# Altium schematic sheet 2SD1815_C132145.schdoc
size 127 x 101 mm
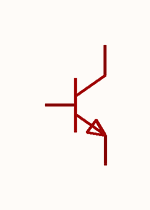
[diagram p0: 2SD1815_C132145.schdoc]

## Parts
Q?  2sd1815(range:100-200)  [TO-252-2_L6.6-W6.1-P4.57-LS9.9-TL-CW]  (value not drawn)

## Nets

Not connected (* = marked no-connect by the designer): Q? 1(B) 2(C) 3(E)

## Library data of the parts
Q? = 2sd1815(range:100-200): 晶体管类型:NPN;集电极电流(Ic):3A;集射极击穿电压(Vceo):100V;耗散功率(Pd):1W;直流电流增益(hFE):100;; Manufacturer: CJ(江苏长电/长晶); Symbol: 2SD1815_C132145; AddInBom: yes; ModelId: ce57f84d66384067af8a68020b6de06d; ModelName: TO-252-2L-3P_L6.6-W6.1-H2.3-LS10.1-P4.6; ModelTransform: 259.842,390.52442,0,270,0,0,38.027,-0.598,0; type: NPN; Current - Collector(Ic): 3A; Collector - Emitter Voltage VCEO: 100V; Pd - Power Dissipation: 1W; DC Current Gain: 100; Transition frequency(fT): 180MHz; Current - Collector Cutoff: 1uA; Vce Saturation(VCE(sat)): 400mV; Emitter-Base Voltage(Vebo): 6V; Number: 1个NPN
